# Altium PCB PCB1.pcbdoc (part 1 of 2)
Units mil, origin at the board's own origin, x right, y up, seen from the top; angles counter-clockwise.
Board outline 4044 x 3540 mil, 2 copper layers (Top Layer, Bottom Layer), stack 2.756 mil thick; 143 components, 117 nets, 519 pads, 194 vias.
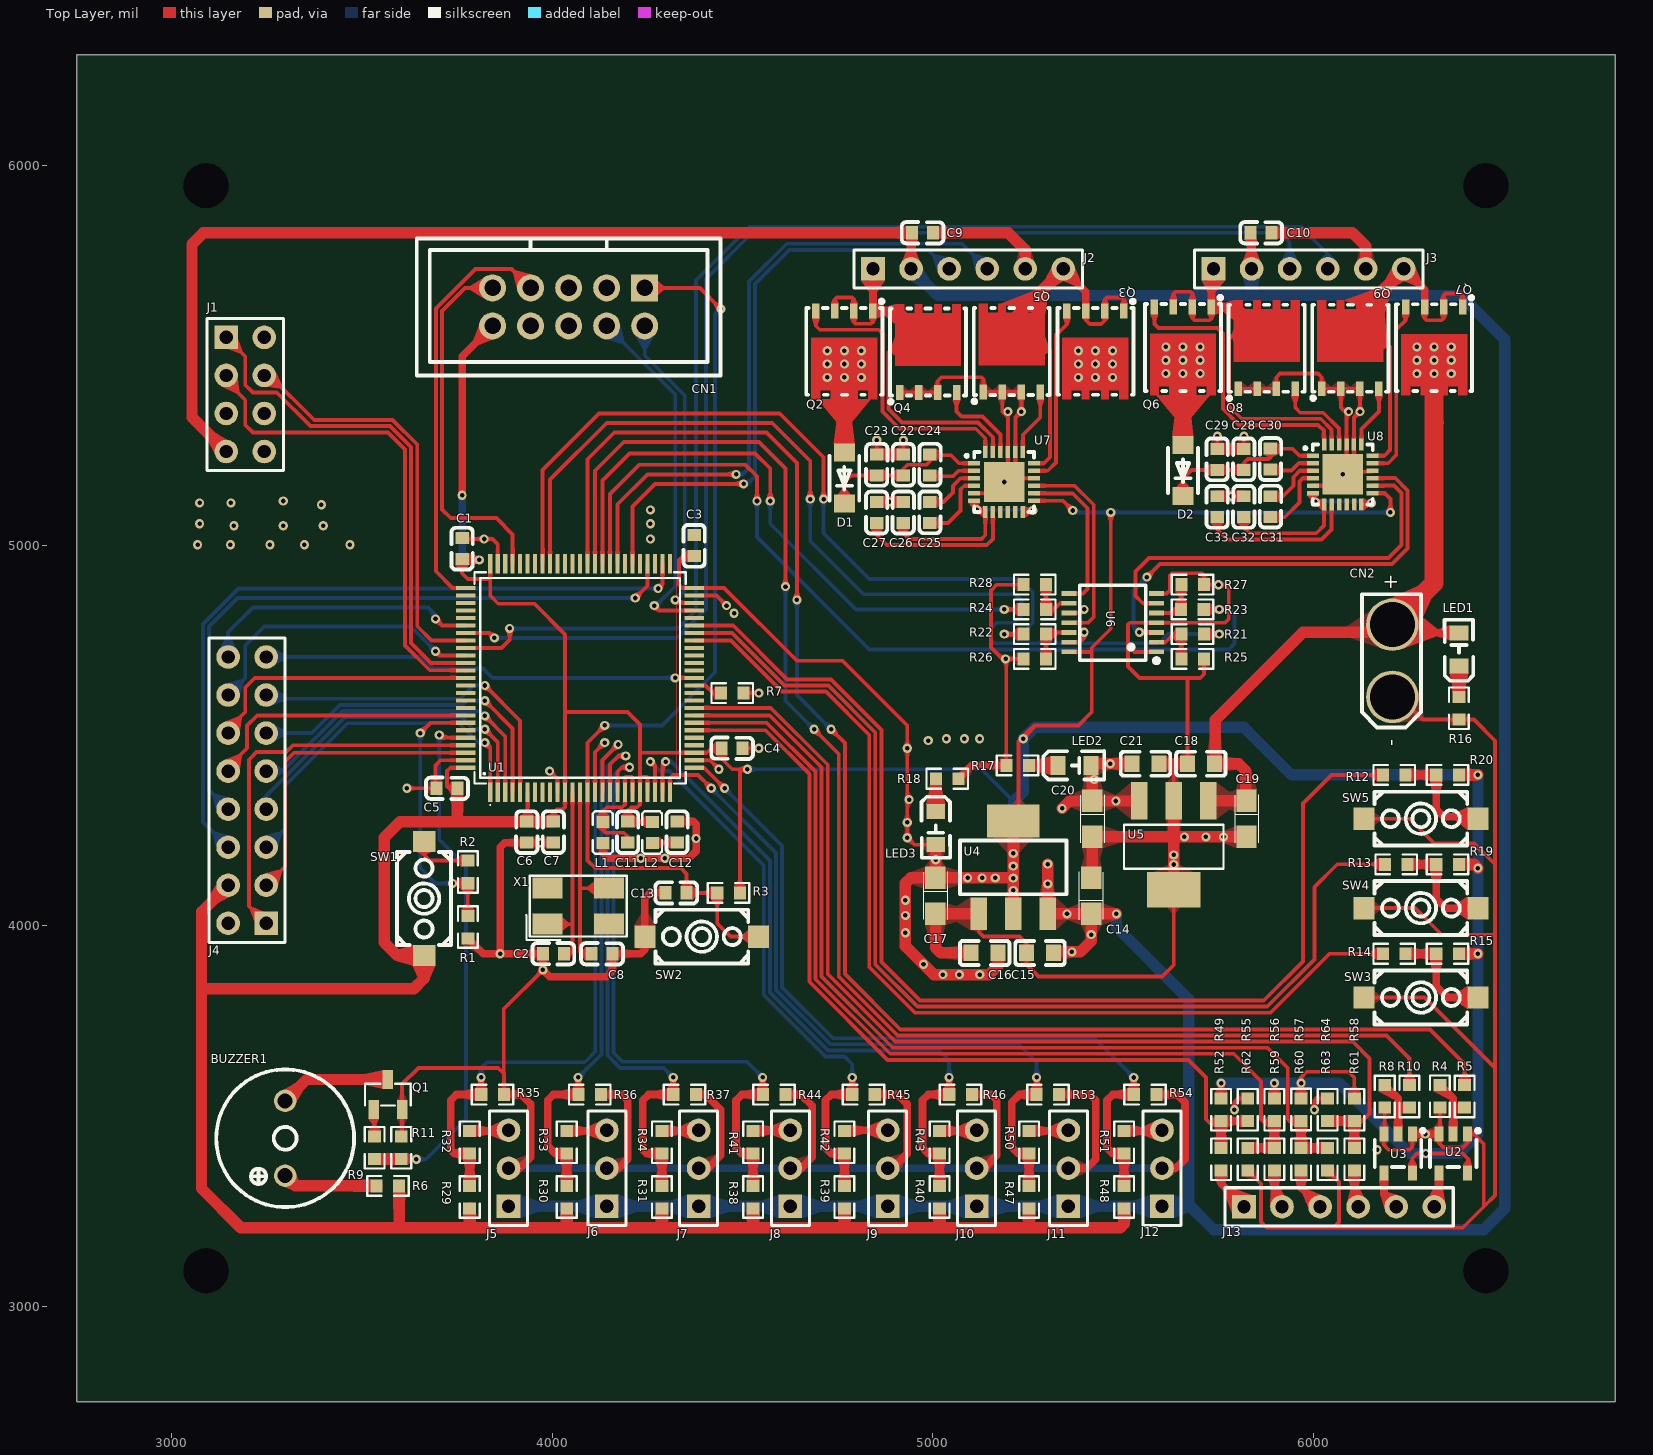
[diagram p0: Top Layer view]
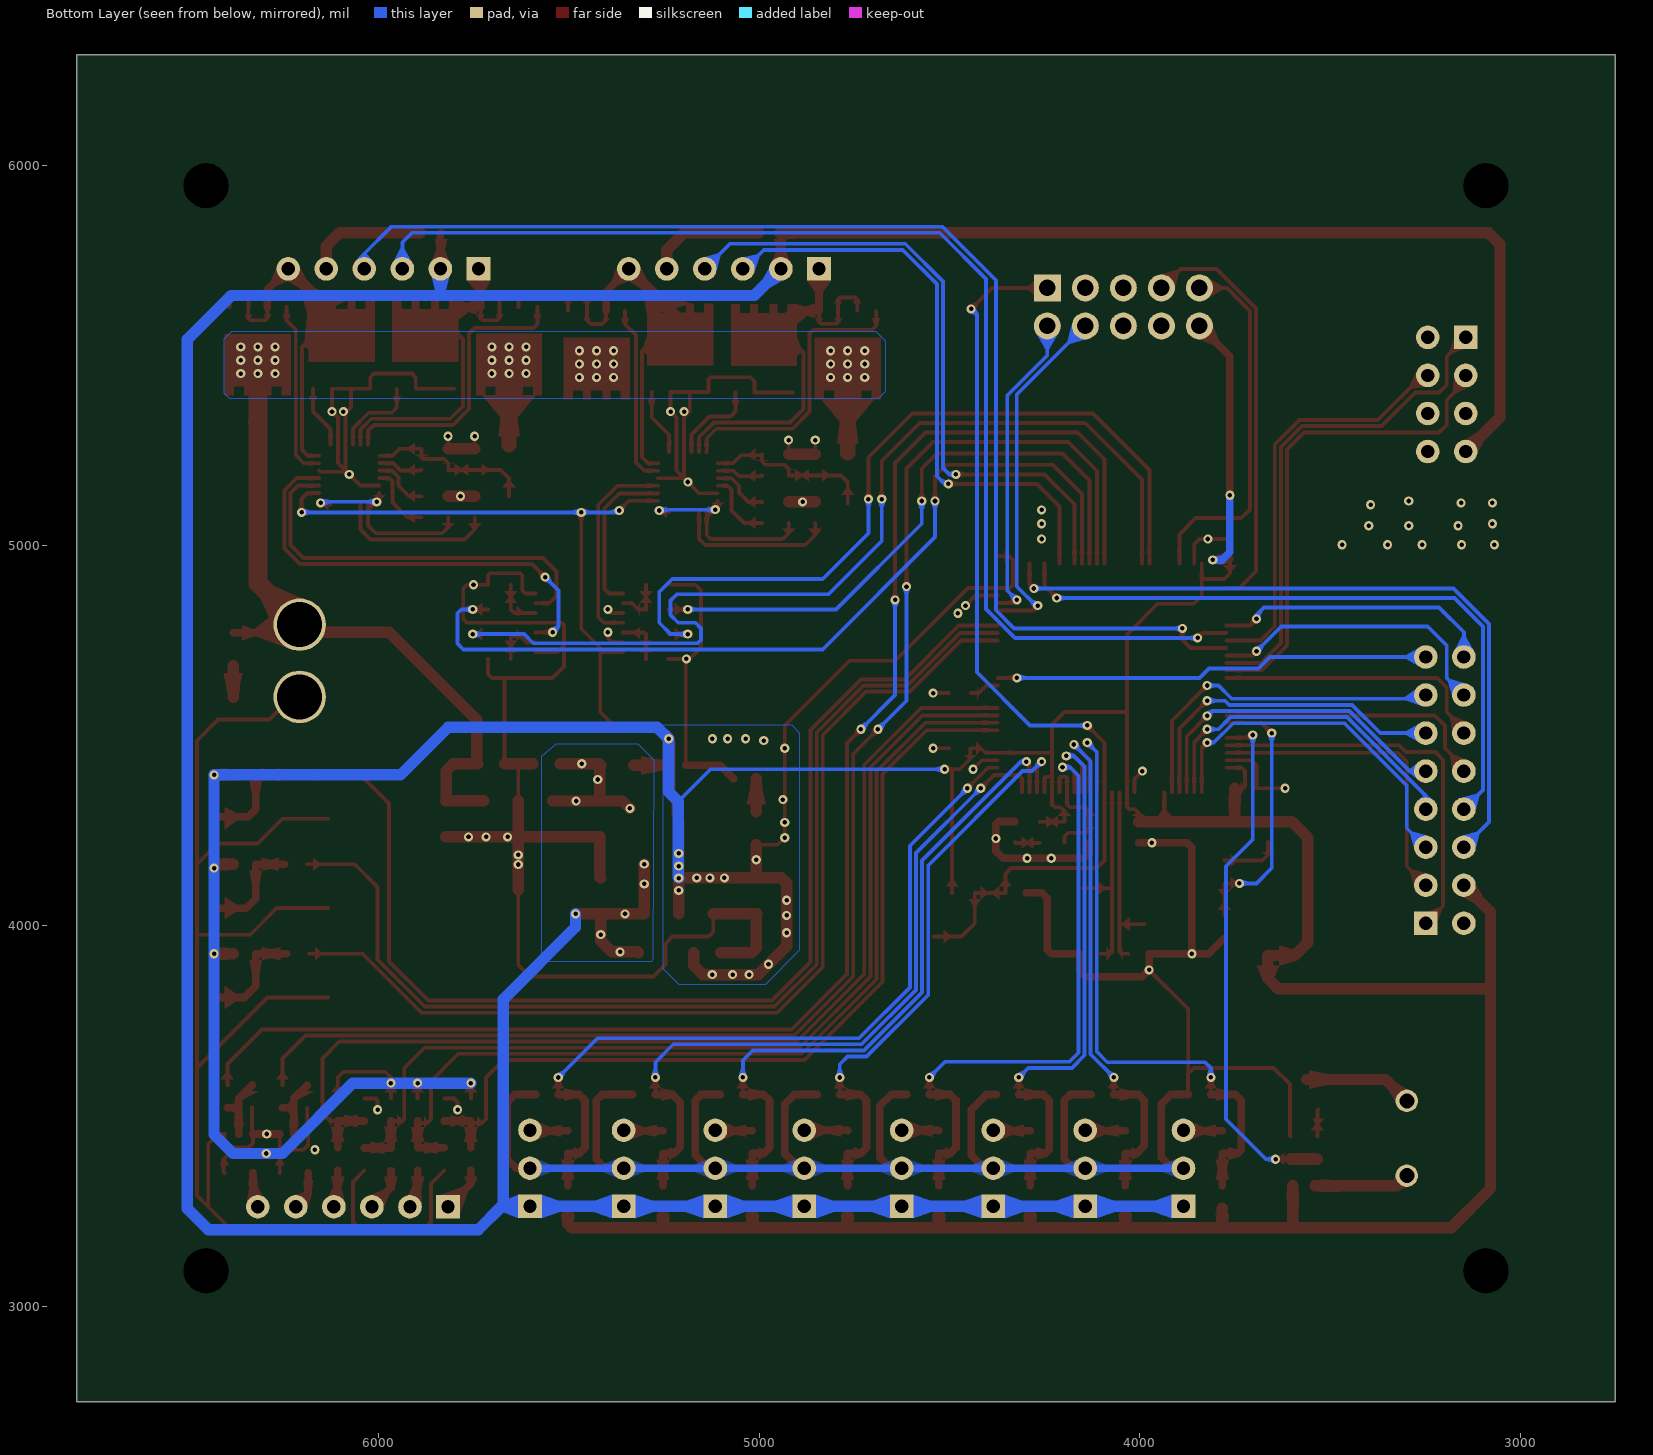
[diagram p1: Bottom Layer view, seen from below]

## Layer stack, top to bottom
Top Layer: signal copper 1.378
Bottom Layer: signal copper 1.378

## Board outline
6794,2750 2750,2750 2750,6290 6794,6290
cut-out: 6513.06,3094 ccw(c6454,3094) 6394.94,3094 ccw(c6454,3094)
cut-out: 3149.06,3094 ccw(c3090,3094) 3030.94,3094 ccw(c3090,3094)
cut-out: 6513.06,5946 ccw(c6454,5946) 6394.94,5946 ccw(c6454,5946)
cut-out: 3149.06,5946 ccw(c3090,5946) 3030.94,5946 ccw(c3090,5946)

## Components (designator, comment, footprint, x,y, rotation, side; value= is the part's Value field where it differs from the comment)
BUZZER1 "Cy-9055-5029" BUZ-TH_BD9.0-P5.00-D0.6-L-FD 3298,3442 r90 top
C1 "100nF" C0603#1 3763,4992 r90 top
C2 "50V 20pF" C0603#1 4003,3927 r0 top
C3 "100nF" C0603#1 4373,4999.44 r90 top
C4 "100nF" C0603#1 4473,4467 r0 top
C5 "100nF" C0603#1 3723,4362 r180 top
C6 "100nF" C0603#1 3933,4246.39 r270 top
C7 "100nF" C0603#1 4003,4246.39 r270 top
C8 "50V 20pF" C0603#1 4130.56,3927 r180 top
C9 "100nF" C0603#1 4973,5822 r180 top
C10 "100nF" C0603#1 5863,5822 r180 top
C11 "100nF" C0603#1 4198,4246.39 r270 top
C12 "100nF" C0603#1 4328,4247 r90 top
C13 "100nF" C0603#1 4325.56,4087 r180 top
C14 "10u" CASE-A_3216 5416.57,4079.09 r90 top
C15 "100nF" C0603#2 5282.01,3929.09 r0 top
C16 "100nF" C0603#2 5136.57,3929.09 r0 top
C17 "10u" CASE-A_3216 5006.57,4079.09 r270 top
C18 "100nF" C0603#2 5704.63,4426.25 r0 top
C19 "10u" CASE-A_3216 5824.63,4281.25 r270 top
C20 "10u" CASE-A_3216 5419.63,4281.25 r270 top
C21 "100nF" C0603#2 5559.2,4426.25 r180 top
C22 "100nF" C0603#1 4922.63,5211.88 r270 top
C23 "10uF" C0603#1 4852.63,5211.88 r270 top
C24 "16V 1uF" C0603#1 4992.63,5211.88 r270 top
C25 "100nF" C0603#1 4992.63,5086.88 r270 top
C26 "6.3V 1uF" C0603#1 4922.63,5086.88 r90 top
C27 "6.3V 1uF" C0603#1 4852.63,5086.88 r90 top
C28 "100nF" C0603#1 5817.42,5226.27 r270 top
C29 "10uF" C0603#1 5747.42,5226.27 r270 top
C30 "16V 1uF" C0603#1 5887.63,5226.88 r270 top
C31 "100nF" C0603#1 5887.63,5101.88 r270 top
C32 "6.3V 1uF" C0603#1 5817.63,5101.88 r90 top
C33 "6.3V 1uF" C0603#1 5747.63,5101.88 r90 top
CN1 "X9555WV-205-PTV01" CONN-TH_X9555WV-2-05-PTV01 4043,5627 r180 top
CN2 "XT30UPB-M" CONN-TH_XT30UPB-M 6208,4697 r90 top
D1 "1N5819HW-7-F" SOD-123_L2.8-W1.8-LS3.7-FD 4767.63,5176.88 r270 top
D2 "1N5819HW-7-F" SOD-123_L2.8-W1.8-LS3.7-FD 5657.63,5196.88 r270 top
J1 "HDR-M-2.54_2x4" HDR-M-2.54_2X4 3193,5397 r270 top
J2 "HDR-M-2.54_1x6" HDR-M-2.54_1X6 5093,5727 r0 top
J3 "HDR-M-2.54_1x6" HDR-M-2.54_1X6 5988,5727 r0 top
J4 "HDR-M-2.54_2x8" HDR-M-2.54_2X8 3198,4357 r90 top
J5 "HDR-M-2.54_1x3" HDR-M-2.54_1X3 3885,3363.15 r90 top
J6 "HDR-M-2.54_1x3" HDR-M-2.54_1X3 4143.42,3363.15 r90 top
J7 "HDR-M-2.54_1x3" HDR-M-2.54_1X3 4384.57,3363.15 r90 top
J8 "HDR-M-2.54_1x3" HDR-M-2.54_1X3 4625.72,3363.15 r90 top
J9 "HDR-M-2.54_1x3" HDR-M-2.54_1X3 4881.61,3363.15 r90 top
J10 "HDR-M-2.54_1x3" HDR-M-2.54_1X3 5115.29,3363.15 r90 top
J11 "HDR-M-2.54_1x3" HDR-M-2.54_1X3 5356.43,3363.15 r90 top
J12 "HDR-M-2.54_1x3" HDR-M-2.54_1X3 5602.58,3363.15 r90 top
J13 "HDR-M-2.54_1x6" HDR-M-2.54_1X6 6068,3262 r0 top
L1 "0Ω" L0603 4133,4245.73 r90 top
L2 "0Ω" L0603 4263,4245.73 r90 top
LED1 "FC-2012HRK-620D" LED0805-RD_RED 6383,4727 r90 top
LED2 "FC-2012HRK-620D" LED0805-RD_RED 5373,4422 r0 top
LED3 "FC-2012HRK-620D" LED0805-RD_RED 5008,4257 r270 top
Q1 "S8050_C908252" SOT-23-3_L2.9-W1.3-P1.90-LS2.4-BR 3568,3557 r270 top
Q2 "TPH1R403NL" POWERVDFN-8_L6.2-W5.2-P1.27-LS6.0-BL 4767.63,5546.88 r180 top
Q3 "TPH1R403NL" POWERVDFN-8_L6.2-W5.2-P1.27-LS6.0-BL 5427.63,5546.88 r180 top
Q4 "TPH1R403NL" POWERVDFN-8_L6.2-W5.2-P1.27-LS6.0-BL 4987.63,5471.88 r0 top
Q5 "TPH1R403NL" POWERVDFN-8_L6.2-W5.2-P1.27-LS6.0-BL 5207.63,5473.38 r0 top
Q6 "TPH1R403NL" POWERVDFN-8_L6.2-W5.2-P1.27-LS6.0-BL 5657.63,5556.88 r180 top
Q7 "TPH1R403NL" POWERVDFN-8_L6.2-W5.2-P1.27-LS6.0-BL 6317.63,5556.77 r180 top
Q8 "TPH1R403NL" POWERVDFN-8_L6.2-W5.2-P1.27-LS6.0-BL 5877.63,5481.88 r0 top
Q9 "TPH1R403NL" POWERVDFN-8_L6.2-W5.2-P1.27-LS6.0-BL 6097.63,5481.88 r0 top
R1 "10k" R0603 3778,3997 r90 top
R2 "1k" R0603 3778,4142 r270 top
R3 "10K" R0603 4463.34,4087 r0 top
R4 "10k" R0603 6333,3552.34 r270 top
R5 "100" R0603 6398,3552 r270 top
R6 "10" R0603 3568,3317 r180 top
R7 "10k" R0603 4473,4612 r180 top
R8 "10k" R0603 6188,3552 r270 top
R9 "4.7K" R0603 3533,3417 r90 top
R10 "100" R0603 6253,3552 r270 top
R11 "10K" R0603 3603,3417.34 r270 top
R12 "470" R0603 6213,4397 r0 top
R13 "470" R0603 6218,4162 r0 top
R14 "470" R0603 6213,3927 r0 top
R15 "4.7k" R0603 6353,3927 r180 top
R16 "1k" R0603 6383,4572 r90 top
R17 "330" R0603 5223,4422 r0 top
R18 "330" R0603 5038,4387 r180 top
R19 "4.7k" R0603 6353,4162 r180 top
R20 "4.7k" R0603 6353,4397 r180 top
R21 "100" R0603 5683,4767 r180 top
R22 "100" R0603 5268,4767 r180 top
R23 "100" R0603 5682.66,4832 r180 top
R24 "100" R0603 5268,4832 r180 top
R25 "10k" R0603 5683,4702 r0 top
R26 "10k" R0603 5268,4702 r0 top
R27 "10k" R0603 5683,4897 r0 top
R28 "10k" R0603 5268,4897 r0 top
R29 "47k" R0603 3783,3287.34 r270 top
R30 "47k" R0603 4038,3287.34 r270 top
R31 "47k" R0603 4288,3287.34 r270 top
R32 "30k" R0603 3783,3431.66 r270 top
R33 "30k" R0603 4038,3431.66 r270 top
R34 "30k" R0603 4288,3431.66 r270 top
R35 "30k" R0603 3843,3557 r180 top
R36 "30k" R0603 4098.34,3557 r180 top
R37 "30k" R0603 4347.66,3557 r180 top
R38 "47k" R0603 4528,3287.34 r270 top
R39 "47k" R0603 4768,3287.34 r270 top
R40 "47k" R0603 5018,3287.34 r270 top
R41 "30k" R0603 4528,3431.66 r270 top
R42 "30k" R0603 4768,3431.66 r270 top
R43 "30k" R0603 5018,3431.66 r270 top
R44 "30k" R0603 4583,3557 r180 top
R45 "30k" R0603 4818,3557 r180 top
R46 "30k" R0603 5073,3557 r180 top
R47 "47k" R0603 5253,3287.34 r270 top
R48 "47k" R0603 5503,3287.34 r270 top
R49 "30k" R0603 5758,3517 r90 top
R50 "30k" R0603 5253,3431.66 r270 top
R51 "30k" R0603 5503,3431.66 r270 top
R52 "30k" R0603 5758,3387 r90 top
R53 "30k" R0603 5302.66,3557 r180 top
R54 "30k" R0603 5558,3557 r180 top
R55 "10k" R0603 5828,3517 r270 top
R56 "30k" R0603 5898,3517 r90 top
R57 "30k" R0603 5968,3517.34 r90 top
R58 "30k" R0603 6108,3517 r90 top
R59 "30k" R0603 5898,3387 r90 top
R60 "30k" R0603 5968,3386.66 r90 top
R61 "30k" R0603 6108,3387 r90 top
R62 "10k" R0603 5828,3387 r90 top
R63 "10k" R0603 6038,3387 r90 top
R64 "10k" R0603 6038,3517 r270 top
SW1 "K2-1107ST-A4SW-06" KEY-SMD_L6.2-W3.6-LS8.0 3663,4072 r270 top
SW2 "K2-1107ST-A4SW-06" KEY-SMD_L6.2-W3.6-LS8.0 4393,3972 r180 top
SW3 "K2-1107ST-A4SW-06" KEY-SMD_L6.2-W3.6-LS8.0 6283,3812 r0 top
SW4 "K2-1107ST-A4SW-06" KEY-SMD_L6.2-W3.6-LS8.0 6283,4047 r0 top
SW5 "K2-1107ST-A4SW-06" KEY-SMD_L6.2-W3.6-LS8.0 6283,4282 r0 top
U1 "CH32V307" CH32V307 4073,4652 r0 top
U2 "SN74LVC1G125DBVR" SOT-23-5_L3.0-W1.7-P0.95-LS2.8-BR 6368,3402 r90 top
U3 "SN74LVC1G125DBVR" SOT-23-5_L3.0-W1.7-P0.95-LS2.8-BR 6223,3402 r90 top
U4 "AMS1117-3.3_C347222" SOT-223_L6.7-W3.5-P2.30-BR 5211.57,4154.1 r270 top
U5 "LM2940S-5.0" SOT-223-3_L6.5-W3.4-P2.30-LS7.0-BR 5633.41,4212.13 r90 top
U6 "SN74HC125PWR" TSSOP-14_L5.0-W4.4-P0.65-LS6.5-BL 5473,4797 r90 top
U7 "DRV8701ERGET" VQFN-24_L4.0-W4.0-P0.50-LS4.0-BL-EP 5187.69,5166.92 r270 top
U8 "DRV8701ERGET" VQFN-24_L4.0-W4.0-P0.50-LS4.0-BL-EP 6077.63,5186.88 r270 top
X1 "8MHz" OSC-SMD_4P-L5.0-W3.2-BL 4068,4052 r0 top

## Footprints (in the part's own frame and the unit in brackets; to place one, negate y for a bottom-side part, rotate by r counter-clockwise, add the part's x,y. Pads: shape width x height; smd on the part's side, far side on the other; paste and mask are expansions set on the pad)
BUZ-TH_BD9.0-P5.00-D0.6-L-FD [mm]
  round 1.5 hole 1: 1(-2.5,0) 2(2.5,0)
  silkscreen extent -4.6,-4.6 4.6,4.6
C0603#1 [mm]
  rect 0.8x0.9 smd: 1(-0.7,0) 2(0.7,0)
  silkscreen extent -1.41,-0.71 1.39,0.72
C0603#2 [mm]
  rect 1x1.1 smd: 1(-0.9,0) 2(0.9,0)
  silkscreen extent -1.65,-0.8 1.65,0.8
CASE-A_3216 [mil]
  rect 59.05x53.5 smd: 1(-47.24,0) 2(47.24,0)
  silkscreen extent -63,-32 63,32
CH32V307 [mm]
  rect 0.28x1.287 smd: 1(-6,-7.628) 2(-5.5,-7.628) 3(-5,-7.628) 4(-4.5,-7.628) 5(-4,-7.628) 6(-3.5,-7.628) 7(-3,-7.628) 8(-2.5,-7.628) 9(-2,-7.628) 10(-1.5,-7.628) 11(-1,-7.628) 12(-0.5,-7.628) 13(0,-7.628) 14(0.5,-7.628) 15(1,-7.628) 16(1.5,-7.628) 17(2,-7.628) 18(2.5,-7.628) 19(3,-7.628) 20(3.5,-7.628) 21(4,-7.628) 22(4.5,-7.628) 23(5,-7.628) 24(5.5,-7.628) 25(6,-7.628) 51(6,7.628) 52(5.5,7.628) 53(5,7.628) 54(4.5,7.628) 55(4,7.628) 56(3.5,7.628) 57(3,7.628) 58(2.5,7.628) 59(2,7.628) 60(1.5,7.628) 61(1,7.628) 62(0.5,7.628) 63(0,7.628) 64(-0.5,7.628) 65(-1,7.628) 66(-1.5,7.628) 67(-2,7.628) 68(-2.5,7.628) 69(-3,7.628) 70(-3.5,7.628) 71(-4,7.628) 72(-4.5,7.628) 73(-5,7.628) 74(-5.5,7.628) 75(-6,7.628)
  rect 1.287x0.28 smd: 26(7.628,-6) 27(7.628,-5.5) 28(7.628,-5) 29(7.628,-4.5) 30(7.628,-4) 31(7.628,-3.5) 32(7.628,-3) 33(7.628,-2.5) 34(7.628,-2) 35(7.628,-1.5) 36(7.628,-1) 37(7.628,-0.5) 38(7.628,0) 39(7.628,0.5) 40(7.628,1) 41(7.628,1.5) 42(7.628,2) 43(7.628,2.5) 44(7.628,3) 45(7.628,3.5) 46(7.628,4) 47(7.628,4.5) 48(7.628,5) 49(7.628,5.5) 50(7.628,6) 76(-7.628,6) 77(-7.628,5.5) 78(-7.628,5) 79(-7.628,4.5) 80(-7.628,4) 81(-7.628,3.5) 82(-7.628,3) 83(-7.628,2.5) 84(-7.628,2) 85(-7.628,1.5) 86(-7.628,1) 87(-7.628,0.5) 88(-7.628,0) 89(-7.628,-0.5) 90(-7.628,-1) 91(-7.628,-1.5) 92(-7.628,-2) 93(-7.628,-2.5) 94(-7.628,-3) 95(-7.628,-3.5) 96(-7.628,-4) 97(-7.628,-4.5) 98(-7.628,-5) 99(-7.628,-5.5) 100(-7.628,-6)
  silkscreen extent -7.05,-8.52 7.05,7.05
CONN-TH_X9555WV-2-05-PTV01 [mm]
  rect 1.8x1.8 hole 1.1: 1(-5.08,-1.27)
  round 1.8 hole 1.1: 2(-5.08,1.27) 3(-2.54,-1.27) 4(-2.54,1.27) 5(0,-1.27) 6(0,1.27) 7(2.54,-1.27) 8(2.54,1.27) 9(5.08,-1.27) 10(5.08,1.27)
  silkscreen extent -10.14,-4.57 10.14,4.57
CONN-TH_XT30UPB-M [mm]
  round 3.5 hole 3: 1(-2.413,0) 2(2.413,0)
  silkscreen extent -4.45,-1.91 4.44,2.03
HDR-M-2.54_1X3 [mil]
  rect 62x62 hole 35: 1(-100,0)
  round 62 hole 35: 2(0,0) 3(100,0)
  silkscreen extent -150,-50 150,50
HDR-M-2.54_1X6 [mil]
  rect 62x62 hole 35: 1(-250,0)
  round 62 hole 35: 2(-150,0) 3(-50,0) 4(50,0) 5(150,0) 6(250,0)
  silkscreen extent -300,-50 300,50
HDR-M-2.54_2X4 [mil]
  rect 62x62 hole 35: 1(-150,-50)
  round 62 hole 35: 2(-150,50) 3(-50,-50) 4(-50,50) 5(50,-50) 6(50,50) 7(150,-50) 8(150,50)
  silkscreen extent -200,-100 200,100
HDR-M-2.54_2X8 [mil]
  rect 62x62 hole 35: 1(-350,-50)
  round 62 hole 35: 2(-350,50) 3(-250,-50) 4(-250,50) 5(-150,-50) 6(-150,50) 7(-50,-50) 8(-50,50) 9(50,-50) 10(50,50) 11(150,-50) 12(150,50) 13(250,-50) 14(250,50) 15(350,-50) 16(350,50)
  silkscreen extent -400,-100 400,100
KEY-SMD_L6.2-W3.6-LS8.0 [mm]
  rect 1.4x1.5 smd: 1(-3.8,0) 2(3.8,0)
  silkscreen extent -3.1,-1.8 3.1,1.8
L0603 [mm]
  rect 0.8x0.864 smd: 1(-0.7,0) 2(0.7,0)
  silkscreen extent -1.42,-0.65 1.41,0.67
LED0805-RD_RED [mm]
  rect 1x1.25 smd: 1(-1.1,0) 2(1.1,0)
  silkscreen extent -2.1,-0.95 1.98,0.96
OSC-SMD_4P-L5.0-W3.2-BL [mm]
  rect 2x1.4 smd: 1(-2.05,-1.2) 2(2.05,-1.2) 3(2.05,1.2) 4(-2.05,1.2)
  silkscreen extent -3.46,-2.26 3.24,2.03
POWERVDFN-8_L6.2-W5.2-P1.27-LS6.0-BL [mm]
  rect 0.5x1 smd: 1(-1.905,-1.775) 2(-0.635,-1.775) 3(0.635,-1.775) 4(1.905,-1.775)
  Top Layer region: -2.2,0.025 -2.2,4.125 -1.6,4.125 -1.6,3.525 -0.9,3.525 -0.9,4.125 -0.4,4.125 -0.4,3.525 0.4,3.525 0.4,4.125 0.9,4.125 0.9,3.525 1.6,3.525 1.6,4.125 2.2,4.125 2.2,0.025
  silkscreen extent -2.61,-2.53 2.54,3.83
R0603 [mil]
  rect 31.75x34.02 smd: 1(-29.66,0) 2(29.66,0)
  silkscreen extent -55,-26 55,26
SOD-123_L2.8-W1.8-LS3.7-FD [mm]
  rect 1.2x1.4 smd: 1(-1.7,0) 2(1.7,0)
  silkscreen extent -1.5,-1 1.5,1
SOT-23-3_L2.9-W1.3-P1.90-LS2.4-BR [mm]
  rect 1.25x0.7 smd: 1(1,-0.95) 2(1,0.95) 3(-1,0)
  silkscreen extent -0.73,-1.53 0.73,1.53
SOT-23-5_L3.0-W1.7-P0.95-LS2.8-BR [mm]
  rect 1x0.6 smd: 1(1.3,-0.95) 2(1.3,0) 3(1.3,0.95) 4(-1.3,0.95) 5(-1.3,-0.95)
  silkscreen extent -0.9,-1.78 1.65,1.55
SOT-223-3_L6.5-W3.4-P2.30-LS7.0-BR [mm]
  rect 2.5x1.1 smd: 1(2.97,-2.3) 2(2.97,0) 3(2.97,2.3)
  rect 2.34x3.6 smd: 4(-2.97,0)
  silkscreen extent -1.57,-3.33 1.37,3.33
SOT-223_L6.7-W3.5-P2.30-BR [mm]
  rect 2.2x1.1 smd: 1(3.099,-2.3) 2(3.099,0) 3(3.099,2.3)
  rect 2.2x3.5 smd: 4(-3.099,0)
  silkscreen extent -1.8,-3.55 1.8,3.55
TSSOP-14_L5.0-W4.4-P0.65-LS6.5-BL [mil]
  rect 12x39 smd: 1(-76.77,-115.16) 2(-51.18,-115.16) 3(-25.59,-115.16) 4(0,-115.16) 5(25.59,-115.16) 6(51.18,-115.16) 7(76.77,-115.16) 8(76.77,115.16) 9(51.18,115.16) 10(25.59,115.16) 11(0,115.16) 12(-25.59,115.16) 13(-51.18,115.16) 14(-76.77,115.16)
  silkscreen extent -106,-121 98,87
VQFN-24_L4.0-W4.0-P0.50-LS4.0-BL-EP [mm]
  rect 0.3x0.8 smd: 1(-1.25,-1.999) 2(-0.751,-2) 3(-0.25,-2) 4(0.25,-2) 5(0.751,-2) 6(1.251,-2) 13(1.25,2) 14(0.749,2) 15(0.249,2) 16(-0.25,2) 17(-0.749,2) 18(-1.25,2)
  rect 0.8x0.3 smd: 7(2.001,-1.25) 8(2.001,-0.75) 9(2.001,-0.249) 10(2.001,0.251) 11(2.001,0.752) 12(2.001,1.251) 19(-2.001,1.25) 20(-2.001,0.75) 21(-2.001,0.251) 22(-2.001,-0.248) 23(-2.001,-0.749) 24(-2.001,-1.249)
  rect 2.7x2.7 smd: 25(0.001,-0.002)
  silkscreen extent -2,-2.6 2,2

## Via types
v1: diameter 24.02, hole 12.01, Top Layer to Bottom Layer, 194 vias

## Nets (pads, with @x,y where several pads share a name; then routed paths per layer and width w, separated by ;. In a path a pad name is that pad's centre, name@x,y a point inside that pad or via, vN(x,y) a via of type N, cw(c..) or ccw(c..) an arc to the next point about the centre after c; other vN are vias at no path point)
$1N7219: R7.2 U1.37 | length 78.4
  Top Layer w10: U1.37@4373.33,4632.31 4402.69,4632.31 4423,4612 R7.2@4443.34,4612
$1N7227: R2.1 SW1.1 | length 156
  Top Layer w10: SW1.1@3663,4221.6 3663,4187 3678,4172 3777.66,4172 R2.1@3778,4171.66
$1N7235: C12.1 L2.1 | length 65.5
  Top Layer w10: L2.1@4263,4218.18 4326.74,4218.18 C12.1@4328,4219.44
$1N7246: Q1.1 R9.2 | length 72
  Top Layer w10: Q1.1@3530.6,3517.63 3533,3515.23 R9.2@3533,3446.66
$1N7247: BUZZER1.2 Q1.3 | length 286.2
  Top Layer w30: BUZZER1.2@3298.01,3540.43 3353.95,3596.37 Q1.3@3561.06,3596.37
$1N7249: BUZZER1.1 R6.2 | length 251.3
  Top Layer w30: BUZZER1.1@3298.01,3343.57 3324.57,3317 R6.2@3538.34,3317
$1N7329: R8.1 R10.2 U3.2 | length 177.3
  Top Layer w20: R8.1@6188,3581.66 6223,3546.66 6223,3512 ; U3.2@6223,3453.18 6223,3512 ; R10.2@6253,3522.34 6233.34,3522.34 6223,3512
$1N7330: R4.1 R5.2 U2.2 | length 177.6
  Top Layer w20: R4.1@6333,3582 6368,3547 6368,3512 ; U2.2@6368,3453.18 6368,3512 ; R5.2@6398,3522.34 6378.34,3522.34 6368,3512
$1N7333: LED1.1 R16.2 | length 82
  Top Layer w30: R16.2@6383,4601.66 LED1.1@6383,4683.69
$1N7338: LED2.1 R17.2 | length 77
  Top Layer w30: R17.2@5252.66,4422 LED2.1@5329.69,4422
$1N7339: LED3.1 R18.2 | length 86.8
  Top Layer w30: LED3.1@5008,4300.31 5008,4386.66 R18.2@5008.34,4387
$1N7389: R14.2 R15.2 SW3.2 | length 287.6
  Top Layer w20: R14.2@6242.66,3927 R15.2@6323.34,3927 6323.34,3841.66 6353,3812 SW3.2@6432.6,3812
$1N7390: R13.2 R19.2 SW4.2 | length 285.5
  Top Layer w20: R13.2@6247.66,4162 R19.2@6323.34,4162 6323.34,4071.66 6348,4047 SW4.2@6432.6,4047
$1N7391: R12.2 R20.2 SW5.2 | length 290.3
  Top Layer w20: R12.2@6242.66,4397 R20.2@6323.34,4397 6323.34,4307 6343.34,4287 6427.6,4287 SW5.2@6432.6,4282
$2N7099: R22.1 R26.2 U6.12 | length 127
  Top Layer w10: R26.2@5297.66,4702 R22.1@5297.66,4767 5302.07,4771.41 U6.12@5357.84,4771.41
$2N7110: R24.1 R28.2 U6.9 | length 131.9
  Top Layer w10: R28.2@5297.66,4897 R24.1@5297.66,4832 5318,4832 5334.18,4848.18 U6.9@5357.84,4848.18
$2N7113: R23.2 R27.1 U6.5 | length 133.9
  Top Layer w10: U6.5@5588.16,4822.59 5643.59,4822.59 R23.2@5653,4832 5653.34,4832.34 R27.1@5653.34,4897
$2N7115: R21.2 R25.1 U6.2 | length 139
  Top Layer w10: U6.2@5588.16,4745.82 5611.82,4745.82 5628,4762 5648.34,4762 R21.2@5653.34,4767 R25.1@5653.34,4702
$2N7120: C27.1 U7.8 | length 426.1
  Top Layer w10: C27.1@4852.63,5059.32 4852.63,5027.37 4879,5001 5142,5001 5158,5017 5158,5087.98 U7.8@5158.18,5088.16
$2N7121: Q5.4 U7.19 | length 176.8
  Top Layer w10: U7.19@5236.91,5245.68 5236.91,5290.91 5282.63,5336.63 Q5.4@5282.63,5403.5
$2N7122: Q3.4 U7.17 | length 477.1
  Top Layer w10: U7.17@5266.43,5196.42 5302.42,5196.42 5324,5218 5324,5553 5352.63,5581.63 Q3.4@5352.63,5616.77
$2N7124: Q4.4 U7.22 | length 236.3
  Top Layer w10: Q4.4@5062.63,5402 5062.63,5352.37 5076,5339 5131,5339 5177.91,5292.09 U7.22@5177.91,5245.68
$2N7125: Q2.4 U7.24 | length 763.7
  Top Layer w10: Q2.4@4692.63,5616.77 4692.63,5577.37 4703,5567 4858,5567 4868,5557 4868,5352 4913,5307 5113,5307 5138,5282 5138,5246.19 U7.24@5138.51,5245.68
$2N7127: C22.2 C23.2 C24.1 D1.2 U7.1 | length 458.4
  Top Layer w10: D1.2@4767.63,5109.95 4767.63,5166.63 4785.32,5184.32 C23.2@4852.63,5184.32 C22.2@4922.63,5184.32 4922.63,5201.63 4933,5212 4983,5212 4992.63,5221.63 C24.1@4992.63,5239.44 4995.07,5237 5048,5237 5068.87,5216.13 U7.1@5108.97,5216.13
$2N7129: C24.2 U7.2 | length 123.3
  Top Layer w10: C24.2@4992.63,5184.32 4994.95,5182 5053,5182 5067.47,5196.47 U7.2@5108.95,5196.47
$2N7130: C25.1 U7.3 | length 152.4
  Top Layer w10: C25.1@4992.63,5114.44 5028,5114.44 5053,5139.44 5053,5157 5072.78,5176.78 U7.3@5108.95,5176.78
$2N7131: C25.2 U7.4 | length 189
  Top Layer w10: C25.2@4992.63,5059.32 5040.32,5059.32 5073,5092 5073,5147 5083,5157 5108.88,5157 U7.4@5108.95,5157.07
$2N7132: C26.1 U7.6 U7.7 U7.12 | length 541.7
  Top Layer w10: C26.1@4922.63,5059.32 4922.63,5032.37 4938,5017 5128,5017 5138,5027 U7.7@5138,5087.68 ; U7.6@5108.95,5117.68 5108.95,5101.05 5123,5087 5137.32,5087 U7.7@5138,5087.68 ; U7.7@5138.48,5088.16 U7.7@5138,5087.68 ; U7.12@5236.93,5088.16 5259.16,5088.16 v1(5263,5092)
  Bottom Layer w10: v1(5115.8,5094.2) 5260.8,5094.2 v1(5263,5092)
$2N7136: C32.1 U8.6 U8.7 U8.12 | length 536.3
  Top Layer w10: C32.1@5817.63,5074.32 5817.63,5047.37 5833,5032 6008,5032 6028.42,5052.42 U8.7@6028.42,5108.12 6011.88,5108.12 5998.89,5121.11 U8.6@5998.89,5137.64 ; U8.12@6126.87,5108.12 6149.12,5108.12 v1(6153,5112)
  Bottom Layer w10: v1(6005.28,5114.72) 6150.28,5114.72 v1(6153,5112)
$2N7142: C33.1 U8.8 | length 420.2
  Top Layer w10: C33.1@5747.63,5074.32 5747.63,5042.37 5774,5016 6022,5016 6048.12,5042.12 U8.8@6048.12,5108.12
$2N7143: C31.2 U8.4 | length 186
  Top Layer w10: C31.2@5887.63,5074.32 5925.32,5074.32 5964,5113 5964,5168 5973.03,5177.03 U8.4@5998.89,5177.03
$2N7144: C31.1 U8.3 | length 152.2
  Top Layer w10: C31.1@5887.63,5129.44 5920.44,5129.44 5948,5157 5948,5179.37 5965.37,5196.74 U8.3@5998.89,5196.74
$2N7145: C30.2 U8.2 | length 120.3
  Top Layer w10: C30.2@5887.63,5199.32 5889.95,5197 5943,5197 5962.43,5216.43 U8.2@5998.89,5216.43
$2N7146: C28.2 C29.2 C30.1 D2.2 U8.1 | length 451.5
  Top Layer w10: D2.2@5657.63,5129.95 5657.63,5176.63 5679.71,5198.71 C29.2@5747.42,5198.71 C28.2@5817.42,5198.71 5817.42,5216.42 5828,5227 5883,5227 5887.63,5231.63 C30.1@5887.63,5254.44 5945.56,5254.44 5963.91,5236.09 U8.1@5998.91,5236.09
$2N7148: Q6.4 U8.24 | length 758.2
  Top Layer w10: Q6.4@5582.63,5626.77 5582.63,5582.37 5593,5572 5748,5572 5763,5557 5763,5359.37 5805.37,5317 6013,5317 6028,5302 6028,5266.09 U8.24@6028.45,5265.64
$2N7149: Q8.4 U8.22 | length 229.5
  Top Layer w10: Q8.4@5952.63,5412 5952.63,5362.37 5966,5349 6026.25,5349 6068,5307.25 6068,5265.79 U8.22@6067.85,5265.64
$2N7150: Q7.4 U8.17 | length 470
  Top Layer w10: U8.17@6156.37,5216.38 6197.38,5216.38 6218,5237 6218,5567 6242.63,5591.63 Q7.4@6242.63,5626.65
$2N7151: Q9.4 U8.19 | length 165.6
  Top Layer w10: U8.19@6126.85,5265.64 6126.85,5305.85 6173,5352 6173,5411.63 Q9.4@6172.63,5412
ADC-0: J13.1 R52.1 | length 120.2
  Top Layer w20: R52.1@5758,3357.34 5758,3322 J13.1@5818,3262
ADC-0-OUT: R49.1 R52.2 R55.2 U1.31 | length 2342.8
  Top Layer w10: U1.31@4373.33,4514.2 4560.8,4514.2 4676,4399 4676,3853.49 4881.49,3648 5672,3648 5718,3602 5718,3492 5728,3482 5752.66,3482 R49.1@5758,3487.34 ; 5793,3489.93 5795.59,3487.34
  Top Layer w20: R52.2@5758,3416.66 R49.1@5758,3487.34 5795.59,3487.34 R55.2@5828,3487.34
ADC-1: J13.2 R59.1 | length 103.6
  Top Layer w20: R59.1@5898,3357.34 5898,3282 J13.2@5918,3262
ADC-1-OUT: R56.1 R59.2 R62.2 U1.32 | length 2481.4
  Top Layer w10: U1.32@4373.33,4533.89 4563.74,4533.89 4692,4405.63 4692,3860.12 4888.12,3664 5791,3664 5863,3592 5863,3492 5873,3482 5892.66,3482 R56.1@5898,3487.34
  Top Layer w20: R62.2@5828,3416.66 R59.2@5898,3416.66 R56.1@5898,3487.34
ADC-2: J13.3 R60.1 | length 115.7
  Top Layer w20: R60.1@5968,3357 5968,3312 J13.3@6018,3262
ADC-2-OUT: R57.1 R60.2 R63.2 U1.33 | length 2579.7
  Top Layer w10: U1.33@4373.33,4553.57 4571.43,4553.57 4708,4417 4708,3866.75 4894.75,3680 5880,3680 5933,3627 5933,3492 5938,3487 5967.32,3487 R57.1@5968,3487.68
  Top Layer w20: R57.1@5968,3487.68 R60.2@5968,3416.32 6037.66,3416.32 R63.2@6038,3416.66
ADC-3: J13.4 R61.1 | length 99.5
  Top Layer w20: R61.1@6108,3357.34 6108,3272 J13.4@6118,3262
ADC-3-OUT: R58.1 R61.2 R64.2 U1.34 | length 2812.7
  Top Layer w10: U1.34@4373.33,4573.26 4574.37,4573.26 4724,4423.63 4724,3873.37 4901.37,3696 6104,3696 6148,3652 6148,3507 6128,3487 6108.34,3487 R58.1@6108,3487.34
  Top Layer w20: R64.2@6038,3487.34 R58.1@6108,3487.34 R61.2@6108,3416.66
ADC-SONAR-0: R29.1 R32.2 R35.2 U1.15 | length 1707.2
  Top Layer w10: v1(3813,3602) 3813.34,3601.66 R35.2@3813.34,3557 ; U1.15@4112.37,4351.67 4112.37,4456.37 v1(4138,4482)
  Top Layer w20: R29.1@3783,3317 R32.2@3783,3402 3743,3402 3733,3412 3733,3542 3748,3557 R35.2@3813.34,3557
  Bottom Layer w10: v1(3813,3602) 3813,3627 3828,3642 4085.37,3642 4113,3669.63 4113,4457 v1(4138,4482)
ADC-SONAR-1: R30.1 R33.2 R36.2 U1.16 | length 1456.2
  Top Layer w10: v1(4068,3602) 4068.68,3601.32 R36.2@4068.68,3557 ; U1.16@4132.06,4351.67 4132.06,4436.06 v1(4173,4477)
  Top Layer w20: R30.1@4038,3317 R33.2@4038,3402 4008,3402 3988,3422 3988,3542 4003,3557 R36.2@4068.68,3557
  Bottom Layer w10: v1(4068,3602) 4129,3663 4129,4433 v1(4173,4477)
ADC-SONAR-2: R31.1 R34.2 R37.2 U1.17 | length 1539.6
  Top Layer w10: U1.17@4151.74,4351.67 4151.74,4424.88 4173.86,4447 v1(4193,4447) ; R37.2@4318,3557 v1(4318,3602)
  Top Layer w20: R31.1@4288,3317 R34.2@4288,3402 4248,3402 4238,3412 4238,3542 4253,3557 R37.2@4318,3557
  Bottom Layer w10: v1(4193,4447) 4173,4447 4145,4419 4145,3660 4178,3627 4293,3627 v1(4318,3602)
ADC-SONAR-3: R38.1 R41.2 R44.2 U1.18 | length 1671.3
  Top Layer w10: U1.18@4171.43,4351.67 4171.43,4405.43 4183,4417 v1(4203,4417) ; v1(4553,3602) 4553.34,3601.66 R44.2@4553.34,3557
  Top Layer w20: R38.1@4528,3317 R41.2@4528,3402 4498,3402 4483,3417 4483,3542 4498,3557 R44.2@4553.34,3557
  Bottom Layer w10: v1(4203,4417) 4183,4417 4161,4395 4161,3666.63 4184.63,3643 4512,3643 v1(4553,3602)
ADC-SONAR-4: R39.1 R42.2 R45.2 U1.23 | length 1567.2
  Top Layer w10: v1(4258,4432) 4269.85,4420.15 U1.23@4269.85,4351.67 ; v1@4788,3602 v1(4788.34,3601.66) R45.2@4788.34,3557
  Top Layer w20: R39.1@4768,3317 R42.2@4768,3402 4733,3402 4718,3417 4718,3542 4733,3557 R45.2@4788.34,3557
  Bottom Layer w10: v1(4258,4432) 4283,4407 4308,4407 4556,4159 4556,3818.75 4717.75,3657 4768,3657 4788.34,3636.66 v1(4788.34,3601.66)
ADC-SONAR-5: R40.1 R43.2 R46.2 U1.24 | length 1785
  Top Layer w10: U1.24@4289.54,4351.67 4289.54,4423.54 v1(4298,4432) ; v1(5043,3602) 5043.34,3601.66 R46.2@5043.34,3557
  Top Layer w20: R40.1@5018,3317 R43.2@5018,3402 4988,3402 4973,3417 4973,3542 4988,3557 R46.2@5043.34,3557
  Bottom Layer w10: v1(4298,4432) 4312.14,4432 4572,4172.14 4572,3825.37 4724.37,3673 5017,3673 5043,3647 v1(5043,3602)
ADC-SONAR-6: R47.1 R50.2 R53.2 U1.25 | length 1941.1
  Top Layer w10: U1.25@4309.22,4351.67 4309.22,4388.22 4318,4397 4383,4397 v1(4418,4362) ; R53.2@5273,3557 v1(5273,3602)
  Top Layer w20: R47.1@5253,3317 R50.2@5253,3402 5224.72,3402 5208,3418.72 5208,3537 5228,3557 R53.2@5273,3557
  Bottom Layer w10: v1(4418,4362) 4588,4192 4588,3832 4731,3689 5226,3689 5273,3642 v1(5273,3602)
ADC-SONAR-7: R48.1 R51.2 R54.2 U1.26 | length 2093.3
  Top Layer w10: U1.26@4373.33,4415.78 4399.22,4415.78 v1(4453,4362) ; v1@5528,3602 v1(5528.34,3601.66) R54.2@5528.34,3557
  Top Layer w20: R48.1@5503,3317 R51.2@5503,3402 5473,3402 5458,3417 5458,3542 5473,3557 R54.2@5528.34,3557
  Bottom Layer w10: v1(4453,4362) 4604,4211 4604,3838.63 4737.63,3705 5425,3705 v1(5528.34,3601.66)
AOUT_EN: J13.5 U3.4 | length 102.2
  Top Layer w20: U3.4@6185.6,3350.82 6185.6,3294.4 J13.5@6218,3262
AOUT_EN_PWM: R10.1 U1.61 | length 3857.4
  Top Layer w10: U1.61@4112.37,4952.33 4112.37,5196.37 4188,5272 4543,5272 4613,5202 v1(4613,4892) ; v1(4688,4517) 4753,4452 4753,3867 4908,3712 6193,3712 6253,3652 R10.1@6253,3581.66
  Bottom Layer w10: v1(4613,4892) 4613,4592 v1(4688,4517)
AOUT_PH: J13.6 U2.4 | length 94
  Top Layer w20: J13.6@6318,3262 6330.6,3274.6 U2.4@6330.6,3350.82
AOUT_PH_DIR: R5.1 U1.62 | length 4064.8
  Top Layer w10: U1.62@4092.69,4952.33 4092.69,5226.69 4163,5297 4563,5297 4643,5217 v1(4643,4857) ; v1(4733,4517) 4769,4481 4769,3873.63 4914.63,3728 6307,3728 6398,3637 R5.1@6398,3581.66
  Bottom Layer w10: v1(4643,4857) 4643,4607 v1(4733,4517)
B7: J4.10 U1.93 | length 716.4
  Top Layer w10: J4.10@3148,4417 3198,4467 3198,4527 3224.57,4553.57 U1.93@3772.67,4553.57
B9: R9.1 R11.2 U1.96 | length 1395.7
  Top Layer w10: R11.2@3603,3387.68 3642.32,3387.68 v1(3643,3387) ; v1(3703,4502) 3710.48,4494.52 U1.96@3772.67,4494.52
  Top Layer w30: R9.1@3533,3387.34 3602.66,3387.34 R11.2@3603,3387.68
  Bottom Layer w10: v1(3643,3387) 3668,3387 3773,3492 3773,4157 3703,4227 v1(3703,4502)
B13: J4.6 U1.52 | length 1918.8
  Top Layer w10: v1(4278,4887) 4289.54,4898.54 U1.52@4289.54,4952.33
  Bottom Layer w10: J4.6@3148,4207 3082,4273 3082,4793.63 3175.37,4887 v1(4278,4887)
B15: J4.8 U1.54 | length 1755.4
  Top Layer w10: v1(4218,4862) 4250.17,4894.17 U1.54@4250.17,4952.33
  Bottom Layer w10: J4.8@3148,4307 3098,4357 3098,4787 3173,4862 v1(4218,4862)
BOOT0: R1.2 R2.2 U1.94 | length 713.2
  Top Layer w10: v1(3653,4507) 3679.89,4533.89 U1.94@3772.67,4533.89 ; v1(3738,4112) 3777.66,4112 R2.2@3778,4112.34 R1.2@3778,4026.66
  Bottom Layer w10: v1(3653,4507) 3653,4152 3693,4112 v1(3738,4112)
D0: J4.16 U1.81 | length 732
  Top Layer w10: v1(3693,4807) 3710.21,4789.79 U1.81@3772.67,4789.79
  Bottom Layer w10: J4.16@3148,4717 3148,4772 3213,4837 3673,4837 3693,4817 v1(3693,4807)
D2: J1.4 U1.83 | length 1098
  Top Layer w10: J1.4@3243,5447 3257.14,5447 3374.37,5329.77 3580.49,5329.77 3645,5265.25 3645,4787.63 3682.21,4750.42 U1.83@3772.67,4750.42
D4: J4.14 U1.85 | length 780.5
  Top Layer w10: v1(3693,4722) 3703.95,4711.05 U1.85@3772.67,4711.05
  Bottom Layer w10: J4.14@3148,4607 3193,4652 3193,4737 3243,4787 3628,4787 v1(3693,4722)
D5: J1.1 U1.86 | length 1329.7
  Top Layer w10: J1.1@3143,5547 3193,5497 3193,5422 3213,5402 3275.97,5402 3364.2,5313.77 3573.86,5313.77 3629,5258.63 3629,4743.63 3681.26,4691.37 U1.86@3772.67,4691.37
D6: J1.3 U1.87 | length 1299.4
  Top Layer w10: J1.3@3143,5447 3143,5432 3193,5382 3193,5317 3213,5297 3568,5297 3613,5252 3613,4737 3678,4672 3772.35,4672 U1.87@3772.67,4671.68
D7: J4.12 U1.88 | length 718.7
  Top Layer w10: J4.12@3148,4517 3193,4562 3193,4627 3218,4652 U1.88@3772.67,4652
DATA0: J5.3 R32.1 | length 102.8
  Top Layer w20: R32.1@3783,3461.32 3883.17,3461.32 J5.3@3885,3463.15
DATA1: J6.3 R33.1 | length 106.2
  Top Layer w20: R33.1@4038,3461.32 4141.59,3461.32 J6.3@4143.42,3463.15
DATA2: J7.3 R34.1 | length 97.3
  Top Layer w20: R34.1@4288,3461.32 4382.74,3461.32 J7.3@4384.57,3463.15
DATA3: J8.3 R41.1 | length 98.5
  Top Layer w20: R41.1@4528,3461.32 4529.83,3463.15 J8.3@4625.72,3463.15
DATA4: J9.3 R42.1 | length 114.4
  Top Layer w20: R42.1@4768,3461.32 4769.83,3463.15 J9.3@4881.61,3463.15
DATA5: J10.3 R43.1 | length 98
  Top Layer w20: R43.1@5018,3461.32 5113.46,3461.32 J10.3@5115.29,3463.15
DATA6: J11.3 R50.1 | length 104.2
  Top Layer w20: R50.1@5253,3461.32 5354.6,3461.32 J11.3@5356.43,3463.15
DATA7: J12.3 R51.1 | length 100.3
  Top Layer w20: R51.1@5503,3461.32 5600.75,3461.32 J12.3@5602.58,3463.15
E0: J4.1 U1.97 | length 1034
  Top Layer w10: J4.1@3248,4007 3203,4052 3203,4437 3223,4457 3300.37,4457 3318.2,4474.83 U1.97@3772.67,4474.83
E1: J4.3 U1.98 | length 830
  Top Layer w10: J4.3@3248,4107 3298,4157 3298,4432 3321.15,4455.15 U1.98@3772.67,4455.15
E2: J4.5 U1.1 | length 932.9
  Top Layer w10: v1(3823,4482) 3836.78,4468.22 U1.1@3836.78,4351.67
  Bottom Layer w10: J4.5@3248,4207 3298,4257 3298,4369.12 3461.88,4533 3754.37,4533 3805.37,4482 v1(3823,4482)
E3: J4.7 U1.2 | length 888
  Top Layer w10: v1(3823,4517) 3856.47,4483.53 U1.2@3856.47,4351.67
  Bottom Layer w10: J4.7@3248,4307 3248,4341.75 3455.25,4549 3761,4549 3793,4517 v1(3823,4517)
E4: J4.9 U1.3 | length 868.2
  Top Layer w10: v1(3823,4552) 3876.15,4498.85 U1.3@3876.15,4351.67
  Bottom Layer w10: J4.9@3248,4407 3290.63,4407 3448.63,4565 3810,4565 v1(3823,4552)
E5: J4.11 U1.4 | length 880.7
  Top Layer w10: v1(3823,4592) 3895.84,4519.16 U1.4@3895.84,4351.67
  Bottom Layer w10: J4.11@3248,4507 3368,4507 3442,4581 3764.63,4581 3775.63,4592 v1(3823,4592)
E6: J4.13 U1.5 | length 912.3
  Top Layer w10: v1(3823,4632) 3915.52,4539.48 U1.5@3915.52,4351.67
  Bottom Layer w10: J4.13@3248,4607 3258,4597 3758,4597 3793,4632 v1(3823,4632)
E7: J4.15 U1.38 | length 1148.1
  Top Layer w10: v1(4323,4652) U1.38@4373.33,4652
  Bottom Layer w10: J4.15@3248,4707 3658,4707 3688,4677 3818,4677 3843,4652 v1(4323,4652)
ENCODER_L-A: J3.3 U1.82 | length 3200.3
  Top Layer w10: U1.82@3772.67,4770.11 3834.89,4770.11 v1(3848,4757)
  Bottom Layer w10: v1(3848,4757) 4328,4757 4404,4833 4404,5700.37 4525.63,5822 5913,5822 5938,5797 J3.3@5938,5727
ENCODER_L-B: J3.4 U1.84 | length 3319
  Top Layer w10: U1.84@3772.67,4730.74 3866.74,4730.74 3888,4752 v1(3888,4782)
  Bottom Layer w10: v1(3888,4782) 4330.37,4782 4378,4829.63 4378,5697 4519,5838 5967,5838 6038,5767 J3.4@6038,5727
ENCODER_R-A: J2.3 U1.56 | length 1578.2
  Top Layer w10: U1.56@4210.8,4952.33 4210.8,5102.43 4270.37,5162 v1(4503,5162)
  Bottom Layer w10: v1(4503,5162) 4513,5162 4533,5182 4533,5687 4623,5777 4988,5777 5038,5727 J2.3@5043,5727
ENCODER_R-B: J2.4 U1.58 | length 1725.5
  Top Layer w10: U1.58@4171.43,4952.33 4171.43,5108.31 4250.12,5187 v1(4483,5187)
  Bottom Layer w10: v1(4483,5187) 4500.37,5187 4517,5203.63 4517,5693.63 4616.37,5793 5077,5793 J2.4@5143,5727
